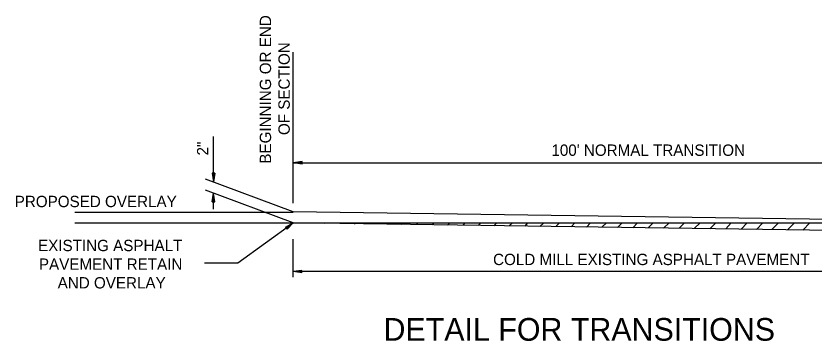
# Model space of a CAD drawing. Extents: x 1373918 to 1374069, y 381000 to 381245.
# Drawn here: x 1373961.35 to 1374003.52, y 381168.05 to 381185.24 of the extents above; entities that cross this region are included whole.
import ezdxf

# ---------------------------------------------------------------- set-up
doc = ezdxf.new("R2010")
doc.units = 0
doc.layers.add('Default', color=7, linetype='Continuous')

msp = doc.modelspace()

# ---------------------------------------------------------------- linework, layer by layer
at = {"layer": 'Default'}
for p, q in [((1373976.005, 381175.34), (1373976.005, 381183.327)), ((1373971.786, 381176.475), (1373971.786, 381178.874)), ((1373976.472, 381177.54), (1373976.005, 381177.474)), ((1373976.005, 381177.474), (1374017.161, 381177.474)), ((1373976.472, 381177.407), (1373976.005, 381177.474)), ((1373976.472, 381177.519), (1373976.073, 381177.474)), ((1373976.472, 381177.407), (1373976.073, 381177.474)), ((1373976.472, 381177.519), (1373976.161, 381177.474)), ((1373976.472, 381177.43), (1373976.161, 381177.474)), ((1373976.472, 381177.496), (1373976.25, 381177.474)), ((1373976.472, 381177.43), (1373976.25, 381177.474)), ((1373976.472, 381177.496), (1373976.317, 381177.474)), ((1373976.472, 381177.452), (1373976.317, 381177.474)), ((1373976.472, 381177.474), (1373976.405, 381177.474)), ((1373976.472, 381177.452), (1373976.405, 381177.474)), ((1373976.472, 381177.407), (1373976.472, 381177.54)), ((1373971.719, 381176.919), (1373971.786, 381176.475)), ((1373971.719, 381176.919), (1373971.786, 381176.541)), ((1373971.852, 381176.919), (1373971.719, 381176.919)), ((1373971.742, 381176.919), (1373971.786, 381176.631)), ((1373971.742, 381176.919), (1373971.786, 381176.696)), ((1373971.763, 381176.919), (1373971.786, 381176.786)), ((1373971.763, 381176.919), (1373971.786, 381176.851)), ((1373971.852, 381176.919), (1373971.786, 381176.475)), ((1373971.807, 381176.919), (1373971.786, 381176.786)), ((1373971.83, 381176.919), (1373971.786, 381176.631)), ((1373971.83, 381176.919), (1373971.786, 381176.541)), ((1373971.807, 381176.919), (1373971.786, 381176.696)), ((1373971.786, 381176.919), (1373971.786, 381176.851)), ((1373976.005, 381174.875), (1373971.364, 381176.608)), ((1373976.005, 381174.298), (1373971.364, 381176.03)), ((1373971.719, 381175.408), (1373971.786, 381175.874)), ((1373971.719, 381175.408), (1373971.786, 381175.808)), ((1373971.742, 381175.408), (1373971.786, 381175.719)), ((1373971.742, 381175.408), (1373971.786, 381175.653)), ((1373971.763, 381175.408), (1373971.786, 381175.564)), ((1373971.852, 381175.408), (1373971.786, 381175.874)), ((1373971.786, 381175.031), (1373971.786, 381175.874)), ((1373971.83, 381175.408), (1373971.786, 381175.808)), ((1373971.83, 381175.408), (1373971.786, 381175.719)), ((1373971.807, 381175.408), (1373971.786, 381175.653)), ((1373971.807, 381175.408), (1373971.786, 381175.564)), ((1373971.719, 381175.408), (1373971.852, 381175.408)), ((1373971.763, 381175.408), (1373971.786, 381175.474)), ((1373971.786, 381175.408), (1373971.786, 381175.474)), ((1373964.457, 381174.874), (1373976.005, 381174.874)), ((1374017.161, 381174.298), (1373976.005, 381174.875)), ((1373964.457, 381174.297), (1374017.161, 381174.297)), ((1373973.075, 381172.188), (1373976.005, 381174.298)), ((1373975.584, 381174.075), (1373976.005, 381174.298)), ((1373975.606, 381174.075), (1373975.939, 381174.254)), ((1373975.672, 381173.965), (1373976.005, 381174.298)), ((1373975.672, 381173.986), (1373975.939, 381174.254)), ((1374017.138, 381173.72), (1373976.005, 381174.298)), ((1373977.625, 381174.275), (1373977.649, 381174.298)), ((1373978.436, 381174.264), (1373978.47, 381174.298)), ((1373979.247, 381174.252), (1373979.314, 381174.298)), ((1373980.078, 381174.241), (1373980.137, 381174.298)), ((1373980.891, 381174.229), (1373980.958, 381174.298)), ((1373981.701, 381174.218), (1373981.78, 381174.298)), ((1373982.512, 381174.207), (1373982.602, 381174.298)), ((1373983.341, 381174.195), (1373983.445, 381174.298)), ((1373984.152, 381174.184), (1373984.268, 381174.298)), ((1373984.985, 381174.172), (1373985.09, 381174.298)), ((1373985.775, 381174.161), (1373985.911, 381174.298)), ((1373986.607, 381174.149), (1373986.755, 381174.298)), ((1373987.416, 381174.138), (1373987.578, 381174.298)), ((1373988.247, 381174.126), (1373988.4, 381174.298)), ((1373989.036, 381174.115), (1373989.243, 381174.298)), ((1373989.871, 381174.104), (1373990.065, 381174.298)), ((1373990.681, 381174.092), (1373990.886, 381174.298)), ((1373991.492, 381174.079), (1373991.709, 381174.297)), ((1373992.301, 381174.069), (1373992.552, 381174.298)), ((1373993.134, 381174.057), (1373993.373, 381174.298)), ((1373993.944, 381174.046), (1373994.195, 381174.298)), ((1373994.754, 381174.035), (1373995.017, 381174.298)), ((1373995.563, 381174.023), (1373995.86, 381174.298)), ((1373996.396, 381174.012), (1373996.682, 381174.298)), ((1373997.184, 381174), (1373997.504, 381174.298)), ((1373998.018, 381173.988), (1373998.327, 381174.298)), ((1373998.849, 381173.977), (1373999.148, 381174.298)), ((1373999.66, 381173.965), (1373999.992, 381174.298)), ((1374000.47, 381173.954), (1374000.813, 381174.298)), ((1374001.281, 381173.943), (1374001.636, 381174.298)), ((1374002.114, 381173.931), (1374002.48, 381174.298)), ((1374002.925, 381173.92), (1374003.302, 381174.298)), ((1373975.584, 381174.075), (1373975.672, 381173.965)), ((1373975.606, 381174.075), (1373975.872, 381174.209)), ((1373975.606, 381174.053), (1373975.804, 381174.164)), ((1373975.606, 381174.053), (1373975.761, 381174.121)), ((1373975.628, 381174.032), (1373975.694, 381174.075)), ((1373975.628, 381174.032), (1373975.694, 381174.075)), ((1373975.65, 381173.986), (1373975.872, 381174.209)), ((1373975.65, 381174.009), (1373975.804, 381174.164)), ((1373975.65, 381174.009), (1373975.761, 381174.121)), ((1373976.005, 381171.432), (1373976.005, 381173.431)), ((1373971.32, 381172.188), (1373973.075, 381172.188)), ((1373976.451, 381171.787), (1373976.005, 381171.722)), ((1373976.451, 381171.787), (1373976.005, 381171.722)), ((1374017.138, 381171.722), (1373976.005, 381171.722)), ((1373976.451, 381171.655), (1373976.005, 381171.722)), ((1373976.451, 381171.655), (1373976.005, 381171.722)), ((1373976.451, 381171.787), (1373976.073, 381171.722)), ((1373976.451, 381171.787), (1373976.073, 381171.722)), ((1373976.451, 381171.677), (1373976.073, 381171.722)), ((1373976.451, 381171.677), (1373976.073, 381171.722)), ((1373976.451, 381171.767), (1373976.161, 381171.722)), ((1373976.451, 381171.767), (1373976.161, 381171.722)), ((1373976.451, 381171.677), (1373976.161, 381171.722)), ((1373976.451, 381171.677), (1373976.161, 381171.722)), ((1373976.451, 381171.767), (1373976.228, 381171.722)), ((1373976.451, 381171.767), (1373976.228, 381171.722)), ((1373976.451, 381171.699), (1373976.228, 381171.722)), ((1373976.451, 381171.699), (1373976.228, 381171.722)), ((1373976.451, 381171.743), (1373976.317, 381171.722)), ((1373976.451, 381171.743), (1373976.317, 381171.722)), ((1373976.451, 381171.699), (1373976.317, 381171.722)), ((1373976.451, 381171.699), (1373976.317, 381171.722)), ((1373976.451, 381171.743), (1373976.384, 381171.722)), ((1373976.451, 381171.743), (1373976.384, 381171.722)), ((1373976.451, 381171.722), (1373976.384, 381171.722)), ((1373976.451, 381171.722), (1373976.384, 381171.722)), ((1373976.451, 381171.655), (1373976.451, 381171.787)), ((1373976.451, 381171.655), (1373976.451, 381171.787))]:
    msp.add_line(p, q, dxfattribs=at)

# ---------------------------------------------------------------- texts
for s, p in [('BEGINNING OR END', (1373974.832, 381177.431)), ('OF SECTION', (1373975.818, 381178.943)), ('2"', (1373971.519, 381177.862))]:
    msp.add_text(s, height=0.6, rotation=90, dxfattribs=at).set_placement(p)
for s, height, p in [("100' NORMAL TRANSITION", 0.6, (1373989.642, 381177.843)), ('PROPOSED OVERLAY', 0.6, (1373961.286, 381175.131)), ('EXISTING ASPHALT', 0.6, (1373962.518, 381172.805)), ('COLD MILL EXISTING ASPHALT PAVEMENT', 0.6, (1373986.56, 381172.068)), ('PAVEMENT RETAIN', 0.6, (1373962.565, 381171.818)), ('AND OVERLAY', 0.6, (1373963.555, 381170.832)), ('DETAIL FOR TRANSITIONS', 1.2, (1373980.772, 381168.07))]:
    msp.add_text(s, height=height, dxfattribs=at).set_placement(p)

doc.saveas('drawing.dxf')
